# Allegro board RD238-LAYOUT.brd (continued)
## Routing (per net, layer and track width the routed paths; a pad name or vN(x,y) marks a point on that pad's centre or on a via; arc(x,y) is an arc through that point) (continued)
NETD352_1: length 7.1
  BOTTOM w0.5: R352.1 42.45,25.8 40,25.8 38.6,24.4 D352.1
NETD353_1: length 11.1
  BOTTOM w0.5: D353.1 93.3,26.75 92.4,25.85 84.9,25.85 R353.1
NETD354_1: length 10.7
  BOTTOM w0.5: R354.1 75.8,94.15 76.75,93.2 D354.1
NETD355_1: length 8.4
  BOTTOM w0.5: R355.1 50.2,93.95 50.95,93.2 D355.1
NETD356_1: length 8.5
  BOTTOM w0.5: D356.1 96.35,93.2 95.6,93.95 R356.1
NETD357_1: length 7.6
  BOTTOM w0.5: R357.1 23.12,94.33 17.93,94.33 D357.1
NETQ201_1: length 3.4
  BOTTOM w0.25: U201.4 25.15,63.35
  BOTTOM w0.3: 25.15,63.35 25.35,63.55 25.35,64.45 R231.2 25.1,66 Q201.1
NETQ202_1: length 12.7
  TOP w0.3: v2(59.3,12.55) R232.2 58.05,13.8 Q202.1
  BOTTOM w0.25: U202.4 51.97,16.4
  BOTTOM w0.3: v2(59.3,12.55) 55.3,16.55 52.12,16.55 51.97,16.4
NETQ203_1: length 14.3
  TOP w0.3: Q203.1 90.3,15.6 R233.2 v2(91.55,12.5)
  BOTTOM w0.25: U203.4 85.67,16.4
  BOTTOM w0.3: v2(91.55,12.5) 91.55,14.65 89.65,16.55 85.82,16.55 85.67,16.4
NETQ204_1: length 19.5
  TOP w0.3: Q204.1 54.45,106.3 R234.2 v2(53.2,107.55)
  BOTTOM w0.25: U204.4 66.65,105.8 66.75,105.9 66.75,106.25 66.5,106.5
  BOTTOM w0.3: 66.5,106.5 65.9,107.1 65.9,108.2 65.3,108.8 54.45,108.8 v2(53.2,107.55)
NETQ205_1: length 13.1
  BOTTOM w0.25: 43.2,106.5 43.45,106.25 43.45,105.9 43.35,105.8 U205.4
  BOTTOM w0.3: 43.2,106.5 42.6,107.1 42.6,108.2 42,108.8 37.03,108.8 36.25,108.02 36.25,106.95 R235.2 35.65,106.35 Q205.1
NETQ206_1: length 19.5
  TOP w0.3: v2(74.8,107.55) R236.2 76.05,106.3 Q206.1
  BOTTOM w0.25: 88.1,106.5 88.35,106.25 88.35,105.9 88.25,105.8 U206.4
  BOTTOM w0.3: 88.1,106.5 87.5,107.1 87.5,108.2 86.9,108.8 76.05,108.8 v2(74.8,107.55)
NETQ207_1: length 16.7
  TOP w0.3: Q207.1 18.3,104.95 R237.2 v2(18.3,107.55)
  BOTTOM w0.25: U207.4 28.45,105.35 28.65,105.55 28.65,105.8 28.5,105.95
  BOTTOM w0.3: 28.5,105.95 27.8,106.65 27.8,108.2 27.2,108.8 19.55,108.8 v2(18.3,107.55)
NETR52_2: length 3
  BOTTOM w0.5: U50.4 80.25,61.95 79.49,62.71 79.25,62.71 78.5,63.46 R52.2
NETR80_1: length 1.2
  TOP w0.3: R81.2 R80.1
NETR80_2: length 4.5
  TOP w0.3: R80.2 R82.2 77.7,61.75 80.15,61.75 U80.4
NETR82_1: length 1.2
  TOP w0.3: R83.2 R82.1
NETR301_1: length 3
  TOP w0.5: v2(21.05,51.94) 20.7,52.29 U301.11
  BOTTOM w0.5: R311.1 26.45,50.7 R301.1 25.3,50.7
  vias: v2(20.1,51.94)
NETR302_1: length 2.4
  TOP w0.5: 50.1,27.06 50.1,27.31 v2(49.75,27.66) ; 50.1,27.06 50.1,26.25 ; 50.1,27.06 v2(50.7,27.66)
NETR303_1: length 8.6
  TOP w0.5: v2(84.4,27.66) 83.81,27.06 U303.11
  BOTTOM w0.5: v2(84.4,27.66) v2(83.45,27.66) 82.45,28.66 ; R313.1 R303.1 82.45,31.6 R333.2 R323.2
NETR304_1: length 2.6
  TOP w0.5: 62.4,93.85 62.4,92.79 v2(62.75,92.44)
  BOTTOM w0.5: v2(61.8,92.44) v2(62.75,92.44) 62.78,92.4
NETR305_1: length 1.6
  TOP w0.5: v2(39.45,92.44) 39.09,92.79 U305.11
  vias: v2(38.5,92.44)
NETR306_1: length 3
  TOP w0.5: v2(84.85,92.44) 84.5,92.79 U306.11
  BOTTOM w0.5: R316.1 85.97,91.43 R306.1
  vias: v2(83.9,92.44)
NETR307_1: length 1.6
  TOP w0.5: v2(25.15,92.44) 24.8,92.79 24.8,93.85
  vias: v2(24.2,92.44)
NETR341_1: length 1.2
  BOTTOM w0.5: R351.2 R341.1
NETR342_1: length 1.2
  BOTTOM w0.5: R352.2 R342.1
NETR343_1: length 1.2
  BOTTOM w0.5: R343.1 R353.2
NETR344_1: length 1.2
  BOTTOM w0.5: R344.1 R354.2
NETR345_1: length 1.2
  BOTTOM w0.5: R345.1 R355.2
NETR346_1: length 1.2
  BOTTOM w0.5: R346.1 R356.2
NETR347_1: length 1.3
  BOTTOM w0.5: R357.2 R347.1

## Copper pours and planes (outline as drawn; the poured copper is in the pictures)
GND on TOP: 5.2,87 4.85,87.35 4.85,88.7 5,88.85 7.55,88.85 7.74,88.66 7.74,87.14 7.6,87
GND on TOP: 89.8,16.65 89.75,16.7 89.75,17.35 92.41,20.01 92.45,20.03 92.51,20.06 92.52,20.07 92.57,20.09 92.61,20.12 92.68,20.16 92.73,20.2 92.79,20.24 96.59,24.04 96.62,24.08 96.65,24.12 96.76,24.28 96.78,24.33 96.81,24.37 96.87,24.52 96.95,24.6 96.95,24.83 96.95,24.89 96.96,24.94 96.96,46.55 96.95,46.6 96.95,46.66 96.95,48.15 98,49.2 98,65.55 97.66,65.89 97.62,65.98 97.45,66.24 97.24,66.45 96.98,66.62 96.7,66.74 96.4,66.8 96.1,66.8 95.8,66.74 95.52,66.62 95.26,66.45 95.11,66.3 88.9,66.3 88.55,66.65 88.55,67.5 88.74,67.69 98.66,67.69 98.99,67.36 98.99,20.29 96.7,18 96.64,18.01 96,18.06 95.36,18.01 94.74,17.86 94.16,17.62 93.61,17.29 93.13,16.87 93.11,16.85 91.04,16.85 90.84,16.65
GND on TOP: 80.34,54.61 80.2,54.75 80.2,57.7 81.55,59.05 81.55,61.96 81.3,62.21 81.3,63.28 80.5,64.08 80.5,65.21 79.65,66.06 79.65,67.4 79.94,67.69 82.16,67.69 82.45,67.4 82.45,62.55 82.1,62.2 82.1,59.95 82.4,59.65 82.65,59.65 82.7,59.7 83.5,59.7 83.7,59.5 83.7,58.45 82.9,57.65 82.9,54.8 82.71,54.61
GND on TOP: 76.06,11.01 61.09,11.01 60.25,11.85 60.25,14.62 59.92,14.95 58.3,14.95 58.25,14.9 57.45,14.9 57.45,16.75 58.19,17.49 76.46,17.49 76.7,17.25 76.7,11.65 ; 1 cut-out
GND on TOP: 3.5,92.55 3.15,92.9 3.15,93.75 2.85,94.05 2.85,95.45 2.41,95.89 2.41,100.53 2.97,101.09 5.85,101.09 6.02,101.12 6.18,101.18 6.31,101.29 8.81,103.79 8.92,103.92 8.98,104.08 9.01,104.25 9.01,104.26 12.75,108 16.95,108 17.15,107.8 17.15,105.3 17.25,105.2 17.25,104.45 17.15,104.35 17.15,104.35 16.37,104.35 15.37,104.37 13.5,102.5 13.16,102.42 12.58,102.18 12.04,101.85 11.56,101.44 8.91,98.79 8.5,98.31 8.17,97.77 7.93,97.19 7.85,96.85 6.8,95.8 6.75,95.77 6.58,95.6 6.55,95.55 6.3,95.3 6.3,92.8 6.05,92.55
GND on TOP: 47.98,103.88 46.88,104.97 46.38,104.97 46.15,105.2 46.15,108.25 45.9,108.5 42.95,108.5 42.4,107.95 42.4,107.35 42.15,107.1 41.5,107.1 41.2,107.4 41.2,108.65 41.55,109 51.9,109 52.1,108.8 52.1,105.45 52.4,105.15 54.95,105.15 55.08,105.02 55.08,104.23 54.73,103.88 49.15,103.88 49.02,103.91 48.78,103.91 48.65,103.88
GND on TOP: 42.66,11.01 9.59,11.01 8.45,12.15 8.45,15.35 5.7,18.1 2.6,18.1 1.01,19.69 1.01,28.11 2.8,29.9 8.55,29.9 9.15,29.3 9.15,22.23 9.14,22.1 9.15,21.93 9.15,20.45 10.16,19.44 10.31,19.26 13.01,16.56 13.19,16.41 14.2,15.4 15.68,15.4 15.85,15.39 39.69,15.39 39.86,15.4 42.05,15.4 43.1,14.35 43.1,12.61 43.05,12.42 43.05,12.18 43.1,11.99 43.1,11.45 ; 1 cut-out
GND on TOP: 76.26,102.61 71.04,102.61 70.55,103.1 70.55,106.15 69.75,106.95 69.75,107.75 69,108.5 66.55,108.5 65.25,107.2 64.6,107.2 64.45,107.35 64.45,108.75 64.7,109 73.65,109 73.85,108.8 73.85,105.5 74.3,105.05 75.8,105.05 75.95,105.2 76.6,105.2 76.65,105.15 76.65,103 ; 1 cut-out
GND on BOTTOM: 22.2,63.7 22,63.9 22,64.95 22.8,65.75 22.8,66.35 22.9,66.45 24.35,66.45 24.35,65.75 23.9,65.3 23.9,64.07 23.8,63.98 23.79,63.98 23.79,63.94 23.55,63.7
GND on BOTTOM: 4.65,27.55 4.4,27.8 4.4,28.65 4.65,28.9 4.65,30.15 4.8,30.3 6.85,30.3 7.05,30.1 7.05,28.95 7.3,28.7 7.3,27.9 6.95,27.55
GND on BOTTOM: 79.45,63.65 79.4,63.7 79.4,67.35 79.7,67.65 81.5,67.65 81.65,67.5 81.65,66.3 80.1,64.75 80.1,63.7 80.05,63.65
GND on BOTTOM: 80.49,53.81 80.15,54.15 80.15,56.2 80.4,56.45 82.95,56.45 83.25,56.75 83.25,60.15 83.6,60.5 84.1,60.5 84.1,60.36 84.15,60.18 84.24,60.02 84.37,59.89 84.53,59.8 84.71,59.75 84.89,59.75 85.07,59.8 85.23,59.89 85.36,60.02 85.45,60.18 85.5,60.36 85.5,60.5 86.25,60.5 86.3,60.45 86.3,59.8 86.53,59.58 87.33,59.58 87.95,58.95 89.45,58.95 90.05,59.55 94.75,59.55 95,59.3 95,57.65 93.45,56.1 86.8,56.1 84.51,53.81
GND on BOTTOM: 12.87,63.45 12.32,64 10.5,64 10.05,64.45 10.05,65.85 10.2,66 11.85,66 12.1,65.75 12.1,65.05 12.29,64.86 13.11,64.86 13.87,64.1 16.9,64.1 17.5,64.7 17.5,66.15 17.55,66.2 18.05,66.2 18.15,66.1 18.15,63.75 17.85,63.45
GND on BOTTOM: 16.1,105.95 15.8,106.25 15.8,107.75 16.05,108 17.15,108 17.3,107.85 17.3,107.1 17.8,106.6 21.3,106.6 21.35,106.55 21.35,106.05 21.25,105.95
GND on BOTTOM: 3.15,97.6 2.95,97.8 2.95,98.7 2.75,98.9 2.75,100.05 2.6,100.2 2.6,100.7 2.9,101 4.6,101 5.05,100.55 5.05,98.9 4.75,98.6 4.75,97.75 4.6,97.6
GND on BOTTOM: 67.55,56.5 67.1,56.95 67.1,59.05 67.4,59.35 70.15,59.35 70.4,59.1 70.4,56.75 70.15,56.5
GND on BOTTOM: 96.7,18 96.64,18.01 96,18.06 95.4,18.66 95.4,22.85 96.59,24.04 96.62,24.08 96.65,24.12 96.76,24.28 96.78,24.33 96.81,24.37 96.87,24.52 96.95,24.6 96.95,24.83 96.95,24.89 96.96,24.94 96.96,46.55 96.95,46.6 96.95,46.66 96.95,48.15 98,49.2 98,65.55 97.66,65.89 97.62,65.98 97.45,66.24 97.24,66.45 96.98,66.62 96.7,66.74 96.4,66.8 96.1,66.8 95.8,66.74 95.52,66.62 95.26,66.45 95.11,66.3 88.9,66.3 88.55,66.65 88.55,67.5 88.74,67.69 98.66,67.69 98.99,67.36 98.99,20.29
GND on CONDUCTIVE2: outline of 819 points within 1.86,11.95 98.99,108.22 ; 20 cut-outs
Net_1 on BOTTOM: 98.99,1.01 1.01,1.01 1.01,8.99 98.99,8.99 ; 4 cut-outs
Net_2 on BOTTOM: 98.99,111.01 1.01,111.01 1.01,118.99 98.99,118.99 ; 3 cut-outs
Net_7 on CONDUCTIVE3: 98.99,1.01 1.01,1.01 1.01,8.99 98.99,8.99 ; 2 cut-outs
Net_8 on CONDUCTIVE3: 98.99,111.01 1.01,111.01 1.01,118.99 98.99,118.99 ; 2 cut-outs
Net_9 on CONDUCTIVE2: 98.99,1.01 1.01,1.01 1.01,8.99 98.99,8.99 ; 2 cut-outs
Net_10 on CONDUCTIVE2: 98.99,111.01 1.01,111.01 1.01,118.99 98.99,118.99 ; 2 cut-outs
Net_11 on TOP: 98.99,1.01 1.01,1.01 1.01,8.99 98.99,8.99 ; 4 cut-outs
Net_12 on TOP: 98.99,111.01 1.01,111.01 1.01,118.99 98.99,118.99 ; 3 cut-outs
NETC10_2 on TOP: 67.45,61.6 67.45,64.55 71.15,64.55 71.15,67.25 71.59,67.69 73.51,67.69 74.05,67.15 74.05,64.55 76.9,64.55 76.9,62.8 76.65,62.55 75,62.55 74.05,61.6
NETC10_2 on TOP: 82.8,61.1 82.7,61.2 82.7,61.95 83.25,62.5 83.25,63.4 83.6,63.75 83.6,66.4 83.7,66.5 86.7,66.5 87.2,66 87.2,62.9 86.5,62.2 85.25,62.2 84.15,61.1
NETC10_2 on BOTTOM: 86.95,60.5 86.84,60.61 86.84,62.46 86.65,62.65 86.25,62.65 86.05,62.85 86.05,63.2 85.58,63.67 81.08,63.67 80.9,63.85 80.9,64.8 82.45,66.35 87.25,66.35 88.4,65.2 88.4,64.6 89.8,63.2 94.5,63.2 95,62.7 95,61.2 94.3,60.5
NETC10_2 on BOTTOM: 67.45,60.5 67.45,62.84 72.69,62.84 72.69,61.85 72.7,61.8 72.7,61.5 70.7,61.5 70.7,61.5 70.7,60.5
NETC10_2 on BOTTOM: 80.95,61.1 80.85,61.2 80.85,62.4 80.75,62.5 80.51,62.5 80.2,62.81 80.2,63.1 80.4,63.3 81.4,63.3 81.55,63.15 81.55,61.2 81.45,61.1
NETC10_2 on CONDUCTIVE2: 80.75,61.5 80.2,62.05 80.2,63.31 80.49,63.6 87,63.6 87.2,63.4 87.2,61.75 86.95,61.5
NETC10_2 on CONDUCTIVE3: 82.1,59 69.12,59 67.45,60.67 67.45,64.3 68.2,65.05 81.4,65.05 82.85,66.5 87.4,66.5 88,65.9 88,61.8 87.6,61.4 84.5,61.4 84.3,61.2 84.23,61.15 84.1,61.02 84.06,60.95 ; 3 cut-outs
NETC55_1 on TOP: 74.7,65.06 74.7,67.4 74.95,67.65 79,67.65 79.1,67.55 79.1,67 78.95,66.85 76.4,66.85 76.2,66.65 76.2,65.06
NETC55_1 on BOTTOM: 74.55,61.35 74.2,61.7 73.35,61.7 73.2,61.85 73.2,63.35 66.91,63.35 66.91,66.86 67.74,67.69 69.36,67.69 69.85,67.2 69.85,64.75 70.05,64.55 73.2,64.55 73.2,64.55 74.7,64.55 74.7,67.69 76.2,67.69 76.2,64.35 76.45,64.1 77.45,64.1 77.6,63.95 77.6,62.95 77.95,62.6 77.95,61.5 77.8,61.35
NETC55_2 on BOTTOM: 71.9,60.05 71.85,60.1 71.85,60.75 71.95,60.85 73.84,60.85 73.95,60.74 73.95,60.15 73.85,60.05
NETC81_1 on TOP: 84.9,59.8 84.55,60.15 82.7,60.15 82.65,60.2 82.65,60.7 82.7,60.75 84.7,60.75 85.6,61.65 87,61.65 88.15,62.8 88.97,62.8 89.55,62.23 89.55,60.3 89.05,59.8
NETC84_2 on TOP: 83.89,53.81 83.65,54.05 83.65,54.7 84.05,55.1 84.05,58 84.25,58.2 88.85,58.2 88.95,58.1 88.95,56.85 88.55,56.45 86.85,56.45 86.2,55.8 86.2,54 86.01,53.81
NETC221_2 on TOP: 87.24,53.81 87.1,53.95 87.1,55.45 87.45,55.8 89.9,55.8 90.2,55.5 90.2,54 90.01,53.81
NETC221_2 on TOP: 4.85,89.6 4.7,89.75 4.7,91.4 4.95,91.65 6.89,91.65 6.95,91.61 7.18,91.55 7.42,91.55 7.48,91.57 7.74,91.31 7.74,89.74 7.6,89.6
NETC221_2 on CONDUCTIVE3: outline of 771 points within 1.82,11.01 98.99,109 ; 38 cut-outs
NETC241_1 on TOP: 16.3,62.3 16,62.6 16,65.15 16.25,65.4 17.65,65.4 18,65.05 18,64.1 18.52,63.58 18.52,62.52 18.3,62.3
NETC241_2 on TOP: 19.15,64 18.9,64.25 18.9,66.7 19.12,66.92 20.52,66.92 20.75,66.7 20.75,64.25 20.5,64
NETC242_1 on TOP: 54.35,14.2 54.1,14.45 52.9,14.45 52.8,14.55 52.8,15.6 52.35,16.05 52.35,17 52.55,17.2 53.05,17.2 53.3,16.95 53.3,16.3 54,15.6 56.1,15.6 56.5,15.2 56.5,14.4 56.3,14.2
NETC242_2 on TOP: 50.15,13.1 50.05,13.2 50.05,15.35 50.3,15.6 51.65,15.6 51.9,15.35 51.9,13.2 51.8,13.1
NETC243_1 on TOP: 88.35,13.75 87.65,14.45 86.6,14.45 86.5,14.55 86.5,15.6 86.05,16.05 86.05,17 86.25,17.2 86.75,17.2 87.3,16.65 88.65,16.65 88.75,16.55 88.75,13.95 88.55,13.75
NETC243_2 on TOP: 83.85,13.1 83.75,13.2 83.75,15.35 84,15.6 85.35,15.6 85.6,15.35 85.6,13.2 85.5,13.1
NETC244_1 on TOP: 59.45,102.9 59.2,103.15 59.2,103.8 58.5,104.5 56.4,104.5 56,104.9 56,105.7 56.1,105.8 57.45,105.8 57.7,106.05 58,106.05 58.4,105.65 59.6,105.65 59.7,105.55 59.7,104.5 60.15,104.05 60.15,103.1 59.95,102.9
NETC244_2 on TOP: 60.85,104.5 60.6,104.75 60.6,106.9 60.7,107 62.35,107 62.45,106.9 62.45,104.75 62.2,104.5
NETC245_1 on TOP: 36,102.65 33.74,104.91 33.74,106.39 33.86,106.44 34.65,105.65 35.8,105.65 35.9,105.55 35.9,104.6 36.92,103.58 36.92,102.83 36.75,102.65
NETC245_2 on TOP: 37.55,104.5 36.7,105.35 36.7,106.55 36.93,106.78 36.95,106.76 37.18,106.7 37.42,106.7 37.65,106.76 37.71,106.8 38.19,106.8 38.25,106.76 38.48,106.7 38.72,106.7 38.95,106.76 39.01,106.8 39.25,106.8 39.45,106.6 39.45,105.05 38.9,104.5
NETC246_1 on TOP: 81.05,102.9 80.94,103.02 80.94,103.23 80.87,103.46 80.8,103.59 80.8,103.8 80.1,104.5 78,104.5 77.6,104.9 77.6,105.7 77.7,105.8 79.05,105.8 79.3,106.05 79.6,106.05 80,105.65 81.2,105.65 81.3,105.55 81.3,104.5 81.75,104.05 81.75,103.1 81.55,102.9
NETC246_2 on TOP: 82.45,104.5 82.2,104.75 82.2,106.9 82.3,107 83.95,107 84.05,106.9 84.05,104.75 83.8,104.5
NETC247_1 on TOP: 17.53,102.62 17.3,102.85 17.3,103.5 17.4,103.6 18.95,103.6 19.55,104.2 19.55,106.28 19.67,106.33 20.35,105.65 21.5,105.65 21.6,105.55 21.6,104.6 22.62,103.58 22.62,102.83 22.45,102.65 21.7,102.65 21.67,102.62
NETC247_2 on TOP: 23.25,104.5 22.4,105.35 22.4,106.55 22.65,106.8 23.34,106.8 23.4,106.76 23.63,106.7 23.87,106.7 24.1,106.76 24.16,106.8 24.95,106.8 25.15,106.6 25.15,105.05 24.6,104.5
NETC321_1 on TOP: 17.39,44.06 17.17,44.28 17.17,53.27 17.85,53.95 18.5,53.95 18.6,53.85 18.6,52.33 18.53,52.26 18.45,52.06 18.45,51.84 18.53,51.64 18.69,51.48 18.74,51.46 19.1,51.1 21.25,51.1 21.6,51.45 21.6,51.56 21.62,51.58 21.69,51.68 21.71,51.8 21.71,52.2 21.69,52.32 21.62,52.42 21.6,52.44 21.6,53.85 21.7,53.95 22.3,53.95 22.4,53.85 22.4,50.75 22,50.35 21.6,50.35 21.35,50.1 21.35,49.2 20.45,48.3 20.45,44.45 20.06,44.06
NETC321_1 on TOP: 28.34,46.66 28.2,46.8 28.2,48.25 28.8,48.85 28.8,51.1 28.95,51.25 29.7,51.25 29.94,51.01 29.94,47.41 29.19,46.66
NETC321_1 on TOP: 54.05,45.4 53.75,45.7 53.75,51.55 49.85,55.45 44.41,55.45 44.4,55.5 44.4,56.1 41.9,56.1 41.5,56.5 41.5,61.2 39.95,62.75 39.95,65.35 40.4,65.8 42.6,65.8 42.69,65.71 42.69,65.05 42.74,64.42 42.88,63.81 43.12,63.23 43.15,63.19 43.15,63.15 43.21,63.09 43.45,62.69 43.86,62.21 48.41,57.66 48.89,57.25 49.29,57.01 49.3,57 49.43,56.92 50.01,56.68 50.62,56.54 51.25,56.49 54.96,56.49 55.75,55.7 55.75,46.05 55.1,45.4
NETC321_1 on CONDUCTIVE2: outline of 84 points within 17.17,44.05 42.7,66.85 ; 3 cut-outs
NETC321_2 on TOP: 25.34,46.66 24.95,47.05 24.95,48.75 25.2,49 25.2,50.7 26.7,52.2 26.7,53.9 26.75,53.95 27.8,53.95 28.05,53.7 28.05,50.5 27.6,50.05 27.6,48.7 27.65,48.65 27.65,48.48 27.7,48.3 27.69,48.25 27.69,47.87 27.65,47.72 27.65,47.48 27.69,47.33 27.69,46.84 27.51,46.66
NETC321_2 on TOP: 40.1,53.05 38.8,54.35 34.81,54.35 34.51,54.05 32.85,54.05 32.63,54.27 32.63,54.73 32.65,54.75 32.65,55.67 35.49,58.51 35.9,58.99 36.23,59.53 36.33,59.78 36.62,60.07 36.62,60.81 36.65,61.2 37.05,61.6 39.75,61.6 39.95,61.4 39.95,57.75 40.65,57.05 40.65,56.25 41.35,55.55 43.75,55.55 43.9,55.4 43.93,55.25 44.04,55.09 44.05,55.08 44.05,53.2 43.9,53.05
NETC321_2 on BOTTOM: 26.75,39 26.56,39.19 26.56,40.75 26.55,40.78 26.56,40.81 26.51,41.2 26.5,41.22 26.5,43.05 26.7,43.25 28.1,43.25 28.4,42.95 28.4,39.2 28.2,39
NETC321_2 on BOTTOM: 26.03,47.2 25.85,47.38 25.85,48.8 25.8,48.85 25.2,48.85 24.95,49.1 24.95,49.35 25.15,49.55 27.3,49.55 27.6,49.85 27.6,50.7 27.7,50.8 28.35,50.8 28.6,50.55 31.1,50.55 31.2,50.45 31.2,49.7 30.85,49.35 30.05,49.35 29.9,49.44 29.67,49.5 29.43,49.5 29.2,49.44 29.05,49.35 28.9,49.44 28.67,49.5 28.43,49.5 28.2,49.44 28,49.32 27.83,49.15 27.71,48.95 27.65,48.72 27.65,47.4 27.45,47.2
NETC321_2 on CONDUCTIVE3: outline of 102 points within 17.55,40.25 35.45,56 ; 3 cut-outs
NETC322_1 on TOP: 61.84,25.51 61.65,25.7 61.65,27.2 62.9,28.45 62.9,30.25 63.65,31 63.65,46.9 64,47.25 65.7,47.25 65.84,47.11 65.84,25.69 65.66,25.51
NETC322_1 on TOP: 52.3,25.55 52.2,25.65 52.2,27.8 51.3,28.7 51.3,28.86 51.22,29.06 51.06,29.22 50.86,29.3 50.64,29.3 50.44,29.22 49.25,28.03 49.25,27.88 49.2,27.77 49.2,27.55 49.25,27.44 49.25,25.75 49.15,25.65 48.5,25.65 48.4,25.75 48.4,28.55 48.6,28.75 48.6,29.75 48.7,29.85 49.25,29.85 49.35,29.95 49.35,32.27 49.68,32.6 51.3,32.6 51.6,32.3 51.6,30.45 53.05,29 53.05,25.65 52.95,25.55
NETC322_1 on TOP: 40.3,28.8 40.13,28.97 40.13,34.43 40.3,34.6 41.85,34.6 42.05,34.4 42.05,28.95 41.9,28.8
NETC322_1 on CONDUCTIVE2: 55.44,25.51 43.59,25.51 40.13,28.97 40.13,33.63 40.8,34.3 42.74,34.3 42.8,34.2 42.71,34.05 42.65,33.82 42.65,33.58 42.71,33.35 42.83,33.15 43,32.98 43.2,32.86 43.43,32.8 43.67,32.8 43.9,32.86 44.05,32.95 44.2,32.86 44.43,32.8 44.67,32.8 44.9,32.86 45.1,32.98 45.27,33.15 45.39,33.35 45.45,33.58 45.45,33.82 45.39,34.05 45.3,34.2 45.36,34.3 54.25,34.3 58.05,30.5 65.5,30.5 65.84,30.16 65.84,25.79 65.56,25.51 58.36,25.51 58.26,25.64 58.3,25.78 58.3,26.02 58.24,26.25 58.15,26.4 58.24,26.55 58.3,26.78 58.3,27.02 58.24,27.25 58.12,27.45 57.95,27.62 57.75,27.74 57.52,27.8 57.28,27.8 57.05,27.74 56.9,27.65 56.75,27.74 56.52,27.8 56.28,27.8 56.05,27.74 55.85,27.62 55.68,27.45 55.56,27.25 55.5,27.02 55.5,26.78 55.56,26.55 55.65,26.4 55.56,26.25 55.5,26.02 55.5,25.78 55.54,25.64 ; 2 cut-outs
NETC322_2 on TOP: 42.85,25.65 42.75,25.75 42.75,34.8 43.05,35.1 44.83,35.1 45.15,34.77 45.15,28.4 44.15,27.4 44.15,25.75 44.05,25.65
NETC322_2 on TOP: 54.39,25.51 54,25.9 54,30.5 54.2,30.7 56.75,30.7 57.92,31.87 57.92,33.77 58.15,33.99 58.15,34 61.1,34 61.95,34.85 62.8,34.85 62.85,34.8 62.85,31.9 62.6,31.65 61.55,31.65 60.95,31.05 60.95,25.95 60.51,25.51
NETC322_2 on BOTTOM: 42.75,30.4 42.5,30.65 42.5,35 42.64,35.14 52.8,35.14 52.83,35.15 52.86,35.14 53.25,35.19 53.29,35.21 53.32,35.21 53.66,35.3 54.95,35.3 57.55,37.9 57.55,40.85 57.7,41 61.1,41 61.15,40.95 61.15,35.8 58.45,33.1 49.4,33.1 47.58,31.28 47.58,30.63 47.35,30.4
NETC322_2 on CONDUCTIVE3: 58.01,25.51 43.79,25.51 43.1,26.2 43.1,34.7 43.45,35.05 54.4,35.05 58.55,30.9 58.55,26.05 ; 2 cut-outs
NETC323_1 on TOP: outline of 99 points within 71.5,25.6 89.54,47.55
NETC323_1 on TOP: 71.8,26.35 71.61,26.54 71.61,29.26 71.7,29.35 74.25,29.35 74.35,29.25 74.35,28.3 74.3,28.25 74.2,28.25 74.2,28.15 73.9,27.85 73.9,26.55 73.7,26.35
NETC323_1 on CONDUCTIVE2: 88.75,25.6 71.85,25.6 71.4,26.05 71.4,29.85 72.75,31.2 85,31.2 85.6,31.8 85.6,33.55 85.95,33.9 89.2,33.9 89.54,33.56 89.54,27.52 89.55,27.46 89.55,26.4 ; 2 cut-outs
NETC323_2 on TOP: 75.35,25.65 74.7,26.3 74.7,27.65 74.8,27.75 75.05,27.75 75.55,28.25 75.55,30.15 75.35,30.35 74.2,30.35 73.6,30.95 73.6,33.55 75.7,35.65 75.7,36.27 76.4,36.97 76.4,38.1 76.5,38.2 77.45,38.2 77.55,38.1 77.55,37.2 77.65,37.2 77.85,37 83.75,37 83.85,36.9 83.85,34.8 83.65,34.6 79.55,34.6 78.8,33.85 78.8,32 78.1,31.3 78.1,28.55 77.85,28.3 77.85,25.75 77.75,25.65
NETC323_2 on BOTTOM: 76.05,30.15 71.3,34.9 71.3,36.4 69.85,37.85 69.85,40.95 70.6,41.7 73.5,41.7 73.9,41.3 73.9,37.4 77.7,33.6 78.55,33.6 78.9,33.25 78.9,33.08 78.96,32.85 78.96,32.55 78.9,32.32 78.9,32.08 78.96,31.85 79.08,31.65 79.25,31.48 79.45,31.36 79.51,31.3 81,31.3 81.3,31 81.3,30.45 81.1,30.25 77.35,30.25 77.25,30.15
NETC324_1 on TOP: outline of 173 points within 57.05,73.1 92.69,94.59
NETC324_1 on TOP: outline of 190 points within 20.55,81.71 64.1,94.59
NETC324_1 on BOTTOM: 55.5,65.65 55.05,66.1 55.05,67.95 55.95,68.85 55.95,74.1 57.6,75.75 57.6,82 57.95,82.35 63.9,82.35 63.95,82.4 63.95,83.3 64.2,83.55 65.55,83.55 65.75,83.35 65.75,81.8 65.66,81.71 62.4,81.71 62.2,81.71 62.17,81.7 62.13,81.71 61.74,81.65 61.71,81.64 61.68,81.64 61.3,81.54 61.27,81.52 61.24,81.52 60.87,81.37 60.84,81.35 60.81,81.34 60.47,81.14 60.45,81.12 60.42,81.1 60.11,80.86 60.08,80.84 60.05,80.82 59.78,80.54 59.76,80.51 59.73,80.49 59.49,80.18 59.48,80.15 59.46,80.12 59.26,79.78 59.25,79.75 59.23,79.72 59.08,79.36 59.07,79.33 59.06,79.3 58.96,78.93 58.95,78.92 58.95,78.87 58.94,78.85 58.89,78.46 58.9,78.43 58.89,78.4 58.89,71.73 58.89,71.7 58.89,66.49 58.05,65.65
NETC324_1 on CONDUCTIVE2: 64.14,81.71 63.85,82 63.85,83.8 64.2,84.15 69.6,84.15 70.65,85.2 70.65,88.5 71.05,88.9 72.75,88.9 73.09,88.56 73.09,82.27 73.09,82.24 73.09,82.23 73.09,82.16 73.07,82.06 73.03,81.97 72.98,81.89 72.91,81.82 72.83,81.77 72.74,81.73 72.64,81.71 72.59,81.71
NETC324_1 on CONDUCTIVE3: 72.15,83.9 59.85,83.9 57.15,86.6 57.15,91.8 57.34,91.99 59.14,91.99 59.44,91.69 59.44,88.6 59.48,88.4 59.5,88.37 59.5,88.25 61.55,86.2 69.76,86.2 70.51,86.95 70.51,88.36 70.74,88.59 72.05,88.59 72.1,88.6 72.7,88.6 73,88.3 73,84.75
NETC324_2 on TOP: 88.25,84.95 88.05,85.15 88.05,91.35 88.95,92.25 88.95,92.65 89.2,92.9 90.2,92.9 90.45,93.15 90.45,94.35 90.55,94.45 91.15,94.45 91.25,94.35 91.25,93 90.8,92.55 90.8,90.55 90.25,90 90.25,88.9 90.05,88.7 90.05,87.1 90.1,87.05 90.1,85.25 90.08,85.22 90.01,85.11 89.94,85.04 89.83,84.97 89.8,84.95
NETC324_2 on TOP: 28.55,84.95 28.35,85.15 28.35,91.35 29.25,92.25 29.25,92.65 29.5,92.9 30.5,92.9 30.75,93.15 30.75,94.35 30.85,94.45 31.45,94.45 31.55,94.35 31.55,93.08 31.23,92.77 31.17,92.67 31.16,92.61 31.1,92.55 31.1,90.55 30.55,90 30.55,88.9 30.35,88.7 30.35,87.1 30.9,86.55 30.9,85.22 30.63,84.95
NETC324_2 on TOP: 57.75,81.7 57.6,81.85 57.6,85.4 59.1,86.9 59.1,88.4 59.25,88.55 61.95,88.55 64.2,86.3 66.05,86.3 67.8,88.05 67.8,91.95 68.35,92.5 68.35,94.4 68.4,94.45 69.6,94.45 69.75,94.3 69.75,86.9 68.2,85.35 68.2,84.2 68.04,84.04 65.51,84.04 65.47,84.05 65.23,84.05 65.19,84.04 64.51,84.04 64.47,84.05 64.23,84.05 64.19,84.04 62.09,84.04 61.55,83.5 59.3,83.5 59.1,83.3 58.85,83.3 58.85,81.95 58.6,81.7
NETC324_2 on TOP: 42.95,84.95 42.65,85.25 42.65,90.7 42.66,90.72 42.66,91.36 43.55,92.25 43.55,92.65 43.8,92.9 44.8,92.9 45.05,93.15 45.05,94.35 45.15,94.45 45.75,94.45 45.85,94.35 45.85,92.91 45.03,92.1 44.97,92 44.96,91.96 44.95,91.95 44.95,91.91 44.94,91.88 44.94,90.45 44.74,90.25 44.74,85.26 44.69,85.21 44.65,85.16 44.62,85.12 44.53,85.03 44.49,85 44.44,84.96 44.43,84.95
NETC324_2 on BOTTOM: 45.25,81.8 45.15,81.9 45.15,84.33 44.63,84.85 43.1,84.85 42.8,85.15 42.8,86.5 41.8,87.5 40.5,87.5 40.2,87.8 40.2,88.85 40.3,88.95 40.35,88.95 40.36,88.96 46.59,88.96 47.2,88.35 47.2,82.15 46.85,81.8
NETC324_2 on BOTTOM: 34.14,81.71 33.6,82.25 33.6,84.01 33.17,84.45 29.3,84.45 28.45,85.3 28.45,86.55 27.75,87.25 26.1,87.25 25.95,87.4 25.95,88.65 26.2,88.9 32.7,88.9 34.4,87.2 34.4,86.1 36.82,83.68 36.82,81.87 36.66,81.71
NETC324_2 on BOTTOM: 85.69,81.71 85.5,81.9 85.5,83.9 85.7,84.1 87.5,84.1 88.15,84.75 88.15,86.55 87.45,87.25 85.8,87.25 85.65,87.4 85.65,88.65 85.9,88.9 92.4,88.9 92.69,88.61 92.69,82.24 92.16,81.71
NETC324_2 on BOTTOM: 71,81.75 70.8,81.95 70.8,83.35 67.25,86.9 67.25,88.45 66.6,89.1 64.19,89.1 64.15,89.14 64.15,89.6 64.25,89.7 69.65,89.7 70.1,89.25 70.1,87.05 70.85,86.3 72.75,86.3 73.09,85.96 73.09,82.27 73.09,82.25 72.59,81.75
NETC324_2 on CONDUCTIVE2: outline of 100 points within 28.55,81.71 92.65,94.59 ; 9 cut-outs
NETC331_2 on TOP: 23.37,44.05 23.31,44.06 23.28,44.05 23.25,44.06 22.39,44.06 21.6,44.85 21.6,48.7 22.1,49.2 22.1,50 22.8,50.7 22.8,53.85 22.9,53.95 23.55,53.95 23.65,53.85 23.65,52.45 24.3,51.8 24.3,48.6 23.75,48.05 23.75,46.7 24.3,46.15 29.4,46.15 30.45,47.2 30.45,51.25 31.6,52.4 39.4,52.4 40,51.8 44.38,51.8 44.65,52.07 44.65,54.1 44.8,54.25 49.33,54.25 49.48,54.1 49.48,52.45 48.9,51.95 47.1,51.95 46.25,51.1 46.25,49.86 36.35,49.86 35.72,49.81 35.11,49.67 34.66,49.48 34.54,49.57 34.49,49.75 34.37,49.95 34.2,50.12 34,50.24 33.77,50.3 33.53,50.3 33.3,50.24 33.1,50.12 32.93,49.95 32.81,49.75 32.75,49.52 32.75,49.28 32.81,49.05 32.93,48.85 33.1,48.68 33.26,48.59 33.3,48.44 33.1,48.21 32.77,47.67 32.53,47.09 32.39,46.48 32.34,45.85 32.39,45.22 32.53,44.61 32.61,44.41 32.25,44.05
NETC332_2 on TOP: 47.25,25.65 47.15,25.75 47.15,27.8 46.55,28.4 46.1,28.4 45.85,28.65 45.85,34.45 46.54,35.14 52.8,35.14 52.83,35.15 52.86,35.14 53.25,35.19 53.29,35.21 53.32,35.21 53.7,35.31 53.73,35.32 53.76,35.33 54.13,35.48 54.15,35.5 54.19,35.51 54.53,35.71 54.55,35.73 54.58,35.74 54.89,35.98 54.92,36.01 54.94,36.03 55.22,36.31 55.24,36.33 55.27,36.36 55.51,36.67 55.52,36.7 55.54,36.72 55.74,37.06 55.75,37.1 55.77,37.12 55.82,37.25 58.1,37.25 58.75,37.9 58.75,40.58 59.07,40.9 62.29,40.9 62.45,40.74 62.45,35.85 62.2,35.6 59.85,35.6 59.05,34.8 57.57,34.8 57.2,34.43 57.2,33.25 56.1,32.15 52.65,32.15 51.65,33.15 49.8,33.15 48.25,31.6 48.25,30.3 47.85,29.9 47.85,28.7 48,28.55 48,25.85 47.8,25.65
NETC333_2 on TOP: 69.4,25.75 69,26.15 69,40.15 69.45,40.6 71.83,40.6 72.25,40.94 72.25,43.4 72.64,43.79 74.51,43.79 74.75,43.55 74.75,35.75 72.2,33.2 72.2,31.3 71.1,30.2 71.1,25.9 70.95,25.75
NETC333_2 on TOP: 80.95,25.65 80.85,25.75 80.85,27.2 80.55,27.5 80.55,27.95 80.25,28.25 79.05,28.25 78.9,28.4 78.9,29.85 79.25,30.2 79.25,31.77 79.27,31.8 79.31,32 79.31,33.46 79.5,33.65 81.05,33.65 81.4,33.3 81.4,30.25 81.2,30.05 81.2,29 81.7,28.5 81.7,25.8 81.55,25.65
NETC333_2 on CONDUCTIVE3: 82.26,25.51 69.74,25.51 68.86,26.39 68.86,33.51 70.35,35 82.05,35 82.9,34.15 82.9,26.15 ; 3 cut-outs
NETC334_2 on TOP: 64.41,86.81 64.1,87.12 64.1,88.4 64.7,89 64.7,92.1 64.55,92.25 64.55,94.4 64.65,94.5 65.15,94.5 65.3,94.35 65.3,93.2 65.6,92.9 65.85,92.9 65.92,92.83 65.99,92.73 66.53,92.18 66.63,92.12 66.95,91.8 66.95,87.95 65.81,86.81
NETC334_2 on TOP: 25.89,84.91 25.65,85.15 25.65,85.75 25.25,86.15 25.25,88.55 25.45,88.75 25.45,90.1 25.45,90.1 25.45,90.42 26.72,91.68 26.78,91.78 26.9,91.9 26.9,94.3 27.05,94.45 27.65,94.45 27.75,94.35 27.75,92.9 28.05,92.6 28.05,91.38 28.04,91.35 28.04,90.29 27.85,90.1 27.84,90.09 27.6,89.85 27.6,88.85 27.2,88.45 27.2,87.1 27.8,86.5 27.8,85.4 27.31,84.91
NETC334_2 on TOP: 85.29,84.91 84.95,85.25 84.95,88.55 85.15,88.75 85.15,90.1 85.15,90.1 85.15,90.42 86.42,91.68 86.48,91.78 86.6,91.9 86.6,94.3 86.75,94.45 87.35,94.45 87.45,94.35 87.45,92.9 87.75,92.6 87.75,91.38 87.74,91.35 87.74,90.29 87.55,90.1 87.54,90.09 87.3,89.85 87.3,88.85 86.9,88.45 86.9,87.1 87.5,86.5 87.5,85.4 87.01,84.91
NETC334_2 on TOP: 39.74,84.91 39.55,85.1 39.55,88.55 39.75,88.75 39.75,89.8 39.8,89.84 39.92,90 39.95,90.2 39.95,90.54 39.96,90.54 39.95,90.58 40.12,90.75 40.4,90.75 40.41,90.76 40.49,90.77 40.59,90.84 41.02,91.27 41.08,91.37 41.1,91.45 41.2,91.55 41.2,94.3 41.35,94.45 41.95,94.45 42.05,94.35 42.05,92.9 42.35,92.6 42.35,90.72 41.9,90.28 41.9,88.85 41.6,88.55 41.6,87 42.1,86.5 42.1,85.4 41.61,84.91
NETC334_2 on TOP: 54.75,73.75 54.61,73.89 54.61,90.93 54.6,90.99 54.6,91.75 54.79,91.94 56.51,91.94 56.64,91.81 56.64,90.4 56.65,90.35 56.65,89.6 57.7,88.55 57.7,86.85 56.85,86 56.85,75.72 56.69,75.56 56.58,75.4 56.54,75.2 56.54,73.94 56.35,73.75
NETC334_2 on CONDUCTIVE3: outline of 112 points within 25.25,81.71 92.65,94.59 ; 9 cut-outs
NETCN11_23 on TOP: 7.56,71.26 2.14,71.26 1.81,71.59 1.81,90.41 1.95,90.55 3.75,90.55 3.85,90.45 3.85,82.75 7.74,78.86 7.74,71.8 7.76,71.46 ; 2 cut-outs
NETCN13_1 on BOTTOM: 19.3,36.25 18.55,37 17.4,37 17.25,37.15 17.25,40.65 17.4,40.8 22.8,40.8 22.95,40.65 22.95,36.95 22.25,36.25
NETCN14_1 on BOTTOM: 62.3,75.75 62.05,76 62.05,78.45 62.27,78.67 62.36,78.69 62.41,78.69 70.41,78.69 70.55,78.55 70.55,77.9 70.35,77.7 70.05,77.7 69.85,77.5 69.85,75.95 69.65,75.75
NETCN15_1 on BOTTOM: 66.64,81.85 66.4,82.09 66.4,83.45 65.88,83.97 65.81,83.97 65.75,84.02 65.55,84.06 64.2,84.06 64,84.02 63.84,83.91 63.8,83.87 63.63,83.7 63.59,83.66 63.48,83.5 63.44,83.3 63.44,82.86 62.84,82.86 62.6,83.1 62.6,90.85 62.35,91.1 62.35,91.5 62.6,91.75 62.85,91.75 63.6,91 63.6,88.55 63.7,88.45 63.7,86.9 63.78,86.82 63.88,86.65 64.05,86.48 64.22,86.38 64.4,86.2 66.85,86.2 68.75,84.3 68.75,82.25 68.35,81.85
NETCN16_1 on BOTTOM: 30.9,39.05 30.7,39.25 30.7,41.7 28.65,43.75 28.15,43.75 28.1,43.76 26.7,43.76 26.65,43.75 24.5,43.75 24.21,43.87 24.18,43.88 24.15,43.89 23.77,43.99 23.74,43.99 23.7,44.01 23.31,44.06 23.28,44.05 23.25,44.06 19.79,44.06 19.5,44.35 19.5,45.9 17.85,47.55 17.85,51.92 18.27,52.35 19.18,52.35 19.27,52.25 19.27,52.17 19.39,52.06 19.39,51.75 19.4,51.72 19.4,48 20.25,47.15 20.25,45.36 20.76,44.85 26.15,44.85 26.75,45.45 29.95,45.45 32.5,42.9 32.5,41.56 32.49,41.51 32.5,41.48 32.49,41.45 32.49,39.19 32.35,39.05
NETCN17_1 on BOTTOM: 35.84,75.81 35.65,76 35.65,78.45 35.89,78.69 44.01,78.69 44.15,78.55 44.15,77.9 43.95,77.7 43.65,77.7 43.45,77.5 43.45,75.95 43.31,75.81
NETCN18_1 on BOTTOM: 52.8,31.45 52.33,31.93 52.33,32.36 52.54,32.58 59.27,32.58 63.65,36.95 63.65,40.75 63.9,41 65.4,41 65.8,40.6 65.8,33.65 63.6,31.45
NETCN19_1 on BOTTOM: 39.94,81.71 39.5,82.15 39.5,83.79 38.65,84.64 38.65,90.58 38.02,91.2 38.02,91.54 38.23,91.75 39.35,91.75 39.58,91.53 39.58,86.9 39.53,86.85 39.41,86.65 39.35,86.42 39.35,86.18 39.41,85.95 39.5,85.8 39.41,85.65 39.35,85.42 39.35,85.18 39.41,84.95 39.53,84.75 39.58,84.7 39.58,84.67 39.85,84.4 42.2,84.4 42.75,83.85 42.75,81.95 42.51,81.71
NETCN20_1 on BOTTOM: 42.6,38.17 42.45,38.33 42.45,39.25 43.2,40 43.2,41.3 43.45,41.55 47.43,41.55 47.47,41.54 52.86,41.54 53.05,41.35 53.05,38.87 52.36,38.17
NETCN21_1 on BOTTOM: 89.37,42.75 89.31,42.76 89.28,42.75 89.25,42.76 81.56,42.76 81.51,42.76 81.42,42.78 81.08,43.12 81.06,43.21 81.06,43.26 81.06,45.56 81.25,45.75 88.8,45.75 88.9,45.65 88.9,44.25 89.2,43.95 89.5,43.95 89.65,43.8 89.65,42.95 89.45,42.75
NETCN22_1 on BOTTOM: 81.3,75.75 81.05,76 81.05,78.45 81.29,78.69 89.41,78.69 89.55,78.55 89.55,77.9 89.35,77.7 89.05,77.7 88.85,77.5 88.85,75.95 88.65,75.75
NETCN23_1 on BOTTOM: 81.39,81.71 81.2,81.9 81.2,83.9 81.45,84.15 83.56,84.15 84.05,84.64 84.05,90.58 83.42,91.2 83.42,91.54 83.63,91.75 84.75,91.75 84.97,91.53 84.97,86.9 84.93,86.85 84.81,86.65 84.75,86.42 84.75,86.18 84.81,85.95 84.9,85.8 84.81,85.65 84.75,85.42 84.75,85.18 84.81,84.95 84.93,84.75 84.97,84.7 84.97,84.47 84.95,84.36 84.9,84.28 84.9,82.05 84.56,81.71
NETCN24_1 on BOTTOM: 82.3,36.8 81.4,37.7 77.05,37.7 76.3,38.45 76.3,41.4 76.6,41.7 78.17,41.7 78.77,41.1 78.88,40.96 78.91,40.93 78.93,40.91 79.21,40.63 79.23,40.61 79.26,40.58 79.51,40.39 80.15,39.75 81.23,39.75 81.29,39.74 81.32,39.75 81.35,39.74 89.04,39.74 89.09,39.74 89.19,39.72 89.28,39.68 89.36,39.63 89.43,39.56 89.48,39.48 89.52,39.39 89.54,39.29 89.54,39.24 89.54,37.19 89.15,36.8
NETCN25_1 on BOTTOM: 20.89,75.81 20.8,75.9 20.8,77.45 20.55,77.7 19.95,77.7 19.85,77.8 19.85,78.55 20,78.7 20.2,78.7 20.5,78.68 20.54,78.68 20.57,78.68 20.71,78.69 28.59,78.69 28.82,78.45 28.82,76 28.64,75.81
NETCN26_1 on BOTTOM: 25.29,81.71 24.35,82.65 24.35,90.58 23.73,91.2 23.73,91.54 23.93,91.75 25.05,91.75 25.27,91.53 25.27,86.51 25.25,86.42 25.25,86.18 25.27,86.09 25.27,85.51 25.25,85.42 25.25,85.18 25.27,85.09 25.27,84.92 25.4,84.8 25.43,84.75 25.6,84.58 25.65,84.55 26.25,83.95 29.23,83.95 29.3,83.94 32.46,83.94 32.7,83.7 32.7,82 32.41,81.71
NETD50_2 on TOP: 78.65,62.7 78.5,62.85 78.5,64 78.12,64.38 78.1,64.38 77.9,64.58 77.9,66.05 78.15,66.3 79.05,66.3 79.14,66.21 79.14,66.06 79.18,65.86 79.28,65.72 79.28,65.47 79.85,64.9 79.85,63 79.55,62.7
NETD52_1 on TOP: 58.26,64.51 52.91,64.51 50.8,66.63 50.8,67.81 51.08,67.84 51.69,67.98 52.27,68.22 52.81,68.55 53.29,68.96 53.7,69.44 54.03,69.98 54.27,70.56 54.37,70.97 54.47,71.16 54.5,71.22 54.53,71.28 54.59,71.54 54.6,71.6 54.61,71.67 54.61,71.76 54.95,72.1 58.65,72.1 58.89,71.86 58.89,71.73 58.89,71.7 58.89,65.14 ; 1 cut-out
NETD53_1 on TOP: 51.75,45.35 51.21,45.89 51.16,46.48 51.02,47.09 50.78,47.67 50.45,48.21 50.04,48.69 49.56,49.1 49.02,49.43 48.44,49.67 47.83,49.81 47.8,49.82 47.8,51.15 48.05,51.4 51.75,51.4 53.2,49.95 53.2,45.7 52.85,45.35
NETD54_1 on TOP: 59.21,42.3 58.8,42.71 58.8,46.9 59.2,47.3 60.9,47.3 61.2,47 61.2,42.71 60.79,42.3
NETD55_1 on TOP: 68.95,41.7 68.86,41.79 68.86,47.21 69.05,47.4 70.6,47.4 70.95,47.05 70.95,41.85 70.8,41.7
NETD321_1 on BOTTOM: 17.4,26.7 17.25,26.85 17.25,29.65 17.4,29.8 18.35,29.8 18.45,29.7 18.45,26.85 18.3,26.7
NETD321_2 on BOTTOM: 17.45,31.25 17.35,31.35 17.35,34.45 17.5,34.6 19.2,34.6 19.25,34.65 19.25,35.3 19.33,35.38 20.12,35.38 20.25,35.25 20.25,31.6 19.9,31.25
NETD322_1 on BOTTOM: 35.7,35.75 35.6,35.85 35.6,38.3 35.75,38.45 36.7,38.45 36.8,38.35 36.8,35.85 36.7,35.75
NETD322_2 on BOTTOM: 40.05,38.4 38.35,40.1 35.7,40.1 35.55,40.25 35.55,41.35 35.8,41.6 40.4,41.6 40.8,41.2 40.8,39.89 41.5,39.19 41.5,38.5 41.4,38.4
NETD323_1 on BOTTOM: 92.8,40.2 92.7,40.3 92.7,42.75 92.85,42.9 93.8,42.9 93.9,42.8 93.9,40.3 93.8,40.2
NETD323_2 on BOTTOM: 90.6,42.9 90.5,43 90.5,43.65 91.25,44.4 91.25,45.7 91.33,45.78 92.1,45.78 92.31,45.8 93.75,45.8 93.9,45.65 93.9,44.65 93.8,44.55 92.7,44.55 92.25,44.1 92.25,43.55 91.6,42.9
NETD324_2 on BOTTOM: 72.15,75.75 72,75.9 72,77.55 71.8,77.75 71.35,77.75 71.17,77.93 71.17,78.48 71.34,78.65 74,78.65 74.5,78.15 74.5,75.85 74.4,75.75
NETD325_1 on BOTTOM: 50.45,75.9 50.35,76 50.35,78.5 50.45,78.6 51.45,78.6 51.55,78.5 51.55,76.05 51.4,75.9
NETD325_2 on BOTTOM: 45.99,75.81 45.9,75.9 45.9,77.55 45.7,77.75 45.25,77.75 45.07,77.93 45.07,78.48 45.24,78.65 47.9,78.65 48.75,77.8 48.75,75.9 48.66,75.81
NETD326_1 on BOTTOM: 95.85,75.8 95.75,75.9 95.75,78.4 95.85,78.5 96.85,78.5 96.95,78.4 96.95,75.95 96.8,75.8
NETD326_2 on BOTTOM: 91.45,75.75 91.3,75.9 91.3,77.55 91.1,77.75 90.65,77.75 90.47,77.93 90.47,78.48 90.64,78.65 93.3,78.65 94.15,77.8 94.15,75.9 94,75.75
NETD327_1 on BOTTOM: 15.9,78.75 15.8,78.85 15.8,81.35 15.9,81.45 16.9,81.45 17,81.35 17,78.9 16.85,78.75
NETD327_2 on BOTTOM: 16.04,75.81 15.76,76.09 15.76,77.06 15.85,77.15 17.09,77.15 17.38,77.44 17.38,78.08 17.65,78.35 17.65,78.6 17.75,78.7 19,78.7 19.1,78.6 19.1,77.75 19.05,77.7 18.7,77.7 18.45,77.45 18.45,75.85 18.41,75.81
NETD331_1 on BOTTOM: 17.76,23.41 17.62,23.55 17.62,24.75 17.85,24.98 20.55,24.98 20.73,24.8 20.73,23.6 20.54,23.41
NETD332_1 on BOTTOM: 35.7,31.25 35.6,31.35 35.6,33.8 35.75,33.95 36.7,33.95 36.8,33.85 36.8,31.35 36.7,31.25
NETD333_1 on BOTTOM: 92.8,35.7 92.7,35.8 92.7,38.25 92.85,38.4 93.8,38.4 93.9,38.3 93.9,35.8 93.8,35.7
NETD335_1 on BOTTOM: 50.45,80.4 50.35,80.5 50.35,83 50.45,83.1 51.45,83.1 51.55,83 51.55,80.55 51.4,80.4
NETD336_1 on BOTTOM: 95.85,80.3 95.75,80.4 95.75,82.9 95.85,83 96.85,83 96.95,82.9 96.95,80.45 96.8,80.3
NETD337_1 on BOTTOM: 15.9,83.25 15.8,83.35 15.8,85.85 15.9,85.95 16.9,85.95 17,85.85 17,83.4 16.85,83.25
NETD341_1 on BOTTOM: 23.02,23.5 22.88,23.65 22.88,24.6 22.98,24.7 25.48,24.7 25.57,24.6 25.57,23.6 25.48,23.5
NETD342_1 on BOTTOM: 35.7,26.75 35.6,26.85 35.6,29.3 35.75,29.45 36.7,29.45 36.8,29.35 36.8,26.85 36.7,26.75
NETD343_1 on BOTTOM: 92.8,31.2 92.7,31.3 92.7,33.75 92.85,33.9 93.8,33.9 93.9,33.8 93.9,31.3 93.8,31.2
NETD345_1 on BOTTOM: 50.45,84.9 50.35,85 50.35,87.5 50.45,87.6 51.45,87.6 51.55,87.5 51.55,85.05 51.4,84.9
NETD346_1 on BOTTOM: 95.85,84.8 95.75,84.9 95.75,87.4 95.85,87.5 96.85,87.5 96.95,87.4 96.95,84.95 96.8,84.8
NETD347_1 on BOTTOM: 15.9,87.75 15.8,87.85 15.8,90.35 15.9,90.45 16.9,90.45 17,90.35 17,87.9 16.85,87.75
NETD361_1 on BOTTOM: 24.05,46 23.96,46.09 23.96,48.21 24.1,48.35 25.15,48.35 25.21,48.34 25.34,48.21 25.34,47.38 25.38,47.18 25.49,47.02 25.67,46.84 25.83,46.73 26.03,46.69 26.51,46.69 26.6,46.6 26.6,46.1 26.5,46
NETD361_2 on BOTTOM: 20.95,46 20.76,46.19 20.76,47.15 20.75,47.2 20.75,49.35 21,49.6 24.25,49.6 24.35,49.5 24.35,49.11 24.24,49 23.48,49 23.35,48.87 23.35,46.15 23.2,46
NETD362_1 on BOTTOM: 60.7,27.55 60.42,27.83 60.42,29.87 60.65,30.1 63.37,30.1 63.65,29.82 63.65,27.95 63.25,27.55
NETD362_2 on BOTTOM: 54.95,27.4 54.75,27.6 54.75,29.8 55,30.05 59.05,30.05 59.75,29.35 59.75,27.75 59.4,27.4 58.3,27.4 57.75,27.95 55.95,27.95 55.4,27.4
NETD363_1 on BOTTOM: 77.95,34.15 77.2,34.9 77.2,36.73 77.42,36.95 81.15,36.95 81.4,36.7 81.4,36.17 81.08,35.85 79,35.85 78.9,35.75 78.9,34.34 78.71,34.15
NETD363_2 on BOTTOM: 81.98,33.35 81.23,34.1 79.72,34.1 79.58,34.25 79.58,35.06 79.67,35.16 81.68,35.16 82.07,35.55 84.65,35.55 84.75,35.45 84.75,33.5 84.6,33.35
NETD364_1 on BOTTOM: 58.6,82.9 58.4,83.1 58.4,85.3 58.69,85.59 61.25,85.59 61.51,85.33 61.51,83.11 61.3,82.9
NETD364_2 on BOTTOM: 59.15,86.15 58.9,86.4 58.9,89.35 59.45,89.9 62.05,89.9 62.09,89.86 62.09,89.29 61.55,88.75 61.55,86.45 61.25,86.15
NETD365_1 on BOTTOM: 37.38,82.67 37.23,82.82 37.23,83.82 34.99,86.06 34.99,86.34 35.2,86.55 36,86.55 36.05,86.5 36.05,86.35 36.3,86.1 37.2,86.1 37.45,85.85 37.45,85.35 38.3,84.5 38.3,82.9 38.1,82.7 37.4,82.7
NETD365_2 on BOTTOM: 36.95,86.8 36.65,87.1 35.3,87.1 35.11,87.29 35.11,90.71 35.25,90.85 37.66,90.85 37.66,90.84 37.8,90.71 37.8,89.97 37.5,89.67 37.5,87 37.3,86.8
NETD366_1 on BOTTOM: 80.6,84.85 80.41,85.04 80.41,87.46 80.55,87.6 82.75,87.6 82.85,87.5 82.85,85.05 82.65,84.85
NETD366_2 on BOTTOM: 80.54,88.11 80.45,88.2 80.45,91.75 80.65,91.95 82.75,91.95 82.85,91.85 82.85,88.25 82.71,88.11 80.55,88.11
NETD367_1 on BOTTOM: 20.48,81.72 20.17,82.03 20.17,82.03 20.17,84.68 20.35,84.86 22.89,84.86 23.12,84.63 23.12,81.92 22.93,81.72
NETD367_2 on BOTTOM: 20.65,85.5 20.17,85.98 20.17,89.17 20.31,89.31 23.29,89.31 23.45,89.15 23.45,88.75 23.19,88.49 23.19,86.73 23.2,86.72 23.2,85.65 23.05,85.5
NETQ50_3 on BOTTOM: 76.1,58.65 75.95,58.8 75.95,60.55 76.15,60.75 77.85,60.75 77.95,60.65 77.95,59.9 77.45,59.4 77.45,58.75 77.35,58.65
NETQ50_4 on BOTTOM: 74.85,56.7 74.7,56.85 74.7,60.6 74.74,60.64 75.37,60.64 75.44,60.55 75.44,58.8 75.48,58.6 75.5,58.57 75.5,56.8 75.4,56.7
NETR52_1 on BOTTOM: 76.95,65 76.8,65.15 76.8,65.7 77.03,65.92 78.67,65.92 78.89,65.71 78.89,65.14 78.75,65
NETR55_2 on BOTTOM: 78.6,57.95 78.35,58.2 78.35,59.55 78.5,59.7 80.4,59.7 80.55,59.55 80.55,58.2 80.3,57.95
NETR57_1 on BOTTOM: 72.21,57.2 71.7,57.2 71.6,57.3 71.6,58.15 72.2,58.75 73.45,58.75 73.5,58.7 73.5,58.1 72.59,58.1 72.3,57.8 72.3,57.29
NETR301_1 on TOP: 19.97,51.54 19.7,51.81 19.7,52.09 20,52.39 20.1,52.39 20.3,52.59 20.3,53.94 20.35,53.99 21.05,53.99 21.1,53.94 21.1,52.51 21.41,52.2 21.41,51.8 21.15,51.54
NETR301_1 on BOTTOM: 24.55,50.25 24.05,50.75 21.55,50.75 21.35,50.95 21.35,51.3 21.1,51.55 19.9,51.55 19.7,51.75 19.7,53.35 20.15,53.8 23.55,53.8 24.2,53.15 24.2,51.75 24.85,51.1 26.8,51.1 27.05,50.85 27.05,50.5 26.8,50.25
NETR302_1 on BOTTOM: 48.74,25.51 48.4,25.85 48.4,30.85 48.5,30.95 49.8,30.95 50.2,30.55 50.2,28.4 50.55,28.05 51.18,28.05 52.25,29.12 52.25,29.85 52.45,30.05 53.4,30.05 53.55,29.9 53.55,25.75 53.31,25.51
NETR303_1 on TOP: 83.51,25.61 83.4,25.72 83.4,27.09 83.09,27.4 83.09,27.8 83.35,28.06 84.53,28.06 84.8,27.79 84.8,27.51 84.5,27.21 84.4,27.21 84.2,27.01 84.2,25.66 84.15,25.61
NETR303_1 on BOTTOM: 85.9,27.15 82.5,27.15 81.95,27.7 81.95,32 82.05,32.1 86.05,32.1 86.3,31.85 86.3,31.63 86.36,31.4 86.48,31.2 86.5,31.18 86.5,27.75 ; 1 cut-out
NETR304_1 on TOP: 61.67,92.04 61.4,92.31 61.4,92.59 61.7,92.89 61.8,92.89 62,93.09 62,94.44 62.05,94.49 62.75,94.49 62.8,94.44 62.8,93.01 63.11,92.7 63.11,92.3 62.85,92.04
NETR304_1 on BOTTOM: 64.1,90.6 63.95,90.75 63.95,91.15 62.99,92.11 62.16,92.11 61.95,91.9 61.95,91.25 61.85,91.15 59.5,91.15 59.4,91.25 59.4,94.35 59.64,94.59 64.6,94.59 64.7,94.48 64.7,93 64.95,92.75 64.95,90.71 64.84,90.6
NETR305_1 on TOP: 38.37,92.04 38.1,92.31 38.1,92.59 38.4,92.89 38.5,92.89 38.7,93.09 38.7,94.44 38.75,94.49 39.45,94.49 39.5,94.44 39.5,93.01 39.64,92.86 39.64,92.66 39.67,92.54 39.69,92.49 39.69,92.39 39.67,92.34 39.65,92.23 39.47,92.06 39.4,92.06 39.32,92.04
NETR305_1 on BOTTOM: 40.15,89.8 40.1,89.85 40.1,91.9 40,92 39.51,92 39.47,92.03 39.35,92.06 38.23,92.06 38.11,92.03 38.07,92 37.76,92 37.76,92 35.2,92 35.1,92.1 35.1,94.5 35.19,94.59 40.91,94.59 41.19,94.31 41.19,89.86 41.13,89.8
NETR306_1 on TOP: 83.77,92.04 83.5,92.31 83.5,92.59 83.8,92.89 83.9,92.89 84.1,93.09 84.1,94.44 84.15,94.49 84.85,94.49 84.9,94.44 84.9,93.01 85.21,92.7 85.21,92.3 84.95,92.04
NETR306_1 on BOTTOM: 85.55,89.8 85.5,89.85 85.5,91.9 85.4,92 84.91,92 84.87,92.03 84.75,92.06 83.8,92.06 83.05,92.8 80.6,92.8 80.5,92.9 80.5,94.5 80.59,94.59 86.31,94.59 86.59,94.31 86.59,89.86 86.53,89.8
NETR307_1 on TOP: 24.07,92.04 23.8,92.31 23.8,92.59 24.1,92.89 24.2,92.89 24.4,93.09 24.4,94.44 24.45,94.49 25.15,94.49 25.2,94.44 25.2,93.01 25.51,92.7 25.51,92.3 25.25,92.04
NETR307_1 on BOTTOM: 25.85,89.8 25.8,89.85 25.8,91.9 25.7,92 25.22,92 25.17,92.03 25.05,92.06 23.93,92.06 23.81,92.03 23.76,92 23.46,92 23.36,91.91 23.25,91.74 23.22,91.54 23.22,91.2 23.25,91.01 23.36,90.84 23.49,90.72 23.44,90.6 20.3,90.6 20.17,90.73 20.17,92.68 20.16,92.75 20.16,92.81 20.15,92.83 20.15,93 20.55,93.4 26.55,93.4 26.8,93.15 26.8,89.8

Small or netless copper shapes (teardrops, artwork), in the pictures only: 6 on TOP, 8 on BOTTOM
